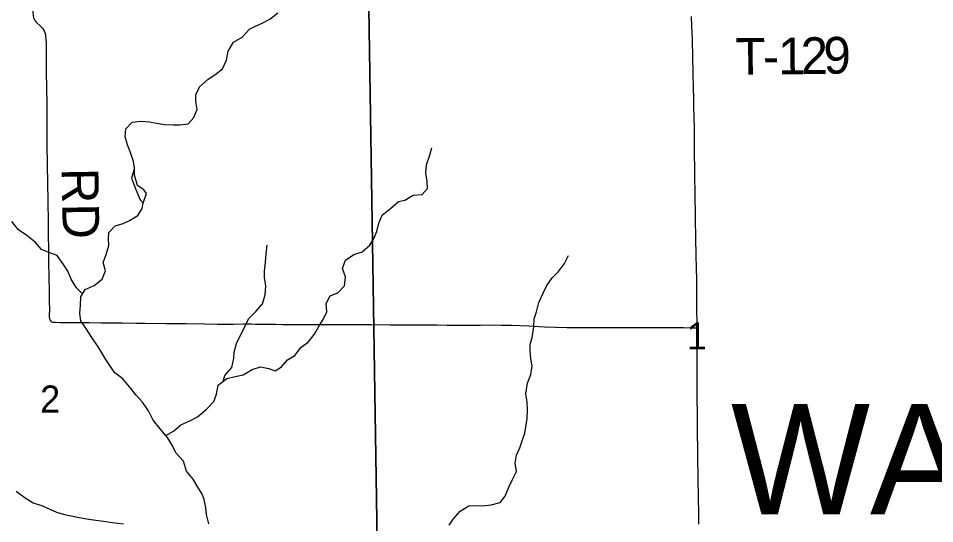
# Model space of a CAD drawing. Extents: x 0 to 1391, y -24 to 440.
# Drawn here: x 356.41 to 384.77, y 312.71 to 328.34 of the extents above; entities that cross this region are included whole.
import ezdxf

# ---------------------------------------------------------------- set-up
doc = ezdxf.new("R2010")
doc.units = 0
for name, color, linetype in [('GM_X_Minor_Lake', 7, 'Continuous'), ('GM_X_Minor_River', 7, 'Continuous'), ('GM_X_Section', 7, 'Continuous'), ('GM_X_Section_Text', 7, 'Continuous'), ('GM_X_Township_Road', 7, 'Continuous'), ('GM_X_Township_Road_Text', 7, 'Continuous'), ('GM_X_Township_Text', 7, 'Continuous')]:
    doc.layers.add(name, color=color, linetype=linetype)

msp = doc.modelspace()

# ---------------------------------------------------------------- linework, layer by layer
at = {"layer": 'GM_X_Minor_Lake'}
for points in [[(360.005, 323.718), (359.918, 323.397), (360.048, 323.045), (360.185, 322.724), (360.279, 322.625)], [(360.279, 322.625), (360.379, 322.917), (360.298, 323.033), (360.103, 323.173), (360.011, 323.486), (360.005, 323.718)]]:
    msp.add_lwpolyline(points, dxfattribs=at)
at = {"layer": 'GM_X_Minor_River'}
for points in [[(363.338, 327.755), (363.564, 328.007), (363.755, 328.102), (363.955, 328.188), (364.193, 328.319), (364.44, 328.51)], [(360.005, 323.718), (359.979, 323.91), (359.894, 324.162), (359.794, 324.423), (359.724, 324.675), (359.738, 324.917), (359.94, 325.133), (360.206, 325.164), (360.471, 325.135), (360.689, 325.092), (360.939, 325.056), (361.219, 325.042), (361.408, 325.045), (361.667, 325.077), (361.846, 325.277), (361.943, 325.518), (361.911, 325.769), (361.908, 325.974), (362.02, 326.222), (362.284, 326.459), (362.491, 326.591), (362.731, 326.782), (362.858, 327.045), (362.903, 327.325), (363.069, 327.602), (363.338, 327.755)], [(360.981, 315.436), (361.212, 315.57), (361.444, 315.762), (361.719, 315.884), (361.957, 316.015), (362.228, 316.244), (362.461, 316.482), (362.543, 316.715), (362.602, 316.987), (362.865, 317.201), (363.124, 317.263), (363.376, 317.31), (363.652, 317.478), (363.904, 317.556), (364.169, 317.511), (364.364, 317.438), (364.556, 317.555), (364.743, 317.771), (364.974, 317.91), (365.17, 318.163), (365.378, 318.318), (365.581, 318.571), (365.724, 318.826), (365.842, 319.02), (365.961, 319.26), (365.937, 319.519), (366.064, 319.751), (366.302, 319.852), (366.504, 320.067), (366.533, 320.34), (366.448, 320.6), (366.538, 320.856), (366.792, 321.039), (367.052, 321.117), (367.292, 321.324), (367.418, 321.526), (367.507, 321.744), (367.574, 322.008), (367.67, 322.256), (367.933, 322.462), (368.181, 322.676), (368.371, 322.717), (368.633, 322.871), (368.913, 322.887), (369.077, 323.08), (369.06, 323.293), (369.028, 323.552), (369.049, 323.81), (369.139, 324.073), (369.206, 324.337)], [(362.31, 312.698), (362.241, 312.995), (362.216, 313.209), (362.169, 313.452), (362.09, 313.644), (361.937, 313.891), (361.82, 314.083), (361.614, 314.331), (361.523, 314.637), (361.286, 314.9), (361.178, 315.138), (361.033, 315.377), (360.804, 315.64), (360.583, 315.911), (360.438, 316.195), (360.255, 316.465), (360.063, 316.682), (359.857, 316.938), (359.644, 317.193), (359.405, 317.373), (359.266, 317.566), (359.105, 317.821), (358.989, 318.013), (358.865, 318.213), (358.689, 318.468), (358.528, 318.722), (358.352, 318.977), (358.32, 319.213), (358.341, 319.463), (358.348, 319.728), (358.482, 319.953), (358.758, 320.075), (359.005, 320.267), (359.11, 320.53), (359.04, 320.79), (359.137, 321.038), (359.219, 321.317), (359.209, 321.514), (359.214, 321.712), (359.408, 321.919), (359.653, 321.997), (359.852, 322.091), (360.113, 322.237), (360.247, 322.454), (360.279, 322.625)], [(358.398, 319.813), (358.218, 320.004), (358.05, 320.266), (357.942, 320.519), (357.789, 320.758), (357.613, 321.005), (357.387, 321.087), (357.132, 321.184), (356.94, 321.416), (356.672, 321.619), (356.419, 321.8), (356.213, 322.055)], [(362.75, 317.107), (362.799, 317.293), (363.017, 317.539), (363.085, 317.825), (363.097, 318.015), (363.164, 318.279), (363.291, 318.534), (363.419, 318.797), (363.538, 319.044), (363.764, 319.274), (363.966, 319.512), (364.057, 319.791), (364.071, 320.056), (364.032, 320.33), (364.029, 320.52), (364.058, 320.8), (364.079, 321.058), (364.116, 321.323)], [(369.742, 312.656), (369.867, 312.851), (370.091, 313.09), (370.351, 313.261), (370.548, 313.265), (370.791, 313.261), (371.05, 313.295), (371.324, 313.359), (371.479, 313.561), (371.597, 313.832), (371.699, 314.058), (371.832, 314.322), (371.791, 314.581), (371.833, 314.823), (371.928, 315.049), (372.015, 315.298), (372.087, 315.51), (372.129, 315.767), (372.155, 315.964), (372.174, 316.237), (372.163, 316.465), (372.114, 316.724), (372.173, 317.057), (372.268, 317.321), (372.31, 317.586), (372.276, 317.807), (372.25, 318.066), (372.253, 318.255), (372.309, 318.467), (372.368, 318.793), (372.379, 319.043), (372.444, 319.262), (372.524, 319.549), (372.642, 319.821), (372.768, 320.077), (372.931, 320.317), (373.131, 320.511), (373.317, 320.759), (373.443, 321.007)], [(356.346, 313.711), (356.622, 313.507), (356.868, 313.357), (357.132, 313.268), (357.364, 313.171), (357.597, 313.067), (357.845, 312.993), (358.049, 312.95), (358.298, 312.899), (358.592, 312.846), (358.811, 312.818), (359.045, 312.782), (359.317, 312.746), (359.665, 312.699)]]:
    msp.add_lwpolyline(points, dxfattribs=at)
at = {"layer": 'GM_X_Section'}
for points in [[(366.91, 328.665), (367.258, 328.65), (367.565, 308.841), (347.482, 309.199), (347.266, 329.014)], [(387.293, 328.839), (387.556, 309.121), (387.563, 308.758), (367.565, 308.841), (367.258, 328.65)]]:
    msp.add_lwpolyline(points, close=True, dxfattribs=at)
at = {"layer": 'GM_X_Township_Road'}
for points in [[(356.872, 328.956), (356.861, 328.521), (356.868, 328.436), (356.887, 328.353), (356.923, 328.277), (356.976, 328.211), (357.094, 328.103), (357.148, 328.05), (357.187, 328), (357.214, 327.957), (357.239, 327.898), (357.253, 327.836), (357.258, 327.789)], [(377.42, 318.762), (377.42, 318.785), (377.414, 319.444), (377.413, 319.555), (377.409, 319.829), (377.405, 320.152), (377.397, 320.711), (377.393, 320.897), (377.39, 321.046), (377.38, 321.506), (377.369, 322.165), (377.365, 322.376), (377.364, 322.5), (377.362, 322.612), (377.359, 322.773), (377.356, 322.947), (377.355, 323.009), (377.35, 323.369), (377.339, 324.475), (377.333, 324.997), (377.329, 325.233), (377.32, 325.668), (377.315, 325.904), (377.309, 326.14), (377.305, 326.314), (377.3, 326.5), (377.293, 326.811), (377.289, 326.972), (377.286, 327.084), (377.271, 327.717), (377.258, 328.102), (377.245, 328.4)], [(357.258, 327.789), (357.265, 327.711), (357.272, 327.574), (357.278, 327.064), (357.278, 326.754), (357.288, 326.108), (357.295, 325.772), (357.299, 325.325), (357.299, 325.064), (357.299, 324.703), (357.301, 324.517), (357.306, 323.722), (357.312, 323.325), (357.316, 323.101), (357.323, 322.841), (357.328, 322.568), (357.334, 322.159), (357.336, 321.985), (357.339, 321.712), (357.347, 321.116), (357.352, 320.768), (357.358, 320.37), (357.365, 319.861), (357.365, 319.81), (357.367, 319.787), (357.373, 319.526), (357.374, 319.389), (357.374, 319.289), (357.372, 319.203), (357.373, 319.105), (357.379, 319.057), (357.391, 319.012), (357.416, 318.974), (357.444, 318.955), (357.477, 318.945), (357.562, 318.936), (357.722, 318.933), (357.958, 318.931), (358.244, 318.931), (358.604, 318.928), (358.977, 318.925), (359.324, 318.922), (359.622, 318.92), (360.057, 318.915), (360.33, 318.91), (360.974, 318.901), (361.247, 318.899), (361.409, 318.898), (361.608, 318.896), (362.179, 318.888), (362.564, 318.882), (362.762, 318.883), (363.073, 318.883), (363.37, 318.887), (363.507, 318.887), (363.619, 318.887), (363.755, 318.884), (363.978, 318.878), (364.027, 318.877), (364.113, 318.877), (364.225, 318.877), (364.262, 318.876), (364.386, 318.875), (364.597, 318.872), (364.82, 318.871), (365.292, 318.87), (365.478, 318.871), (365.739, 318.867), (365.85, 318.867), (366.136, 318.866), (366.384, 318.865), (366.805, 318.866), (367.091, 318.867), (367.314, 318.866), (367.923, 318.862), (368.37, 318.863), (368.818, 318.861), (369.377, 318.854), (369.688, 318.852), (370.284, 318.852), (370.47, 318.853), (370.719, 318.853), (371.017, 318.854), (371.365, 318.853), (371.688, 318.848), (372.21, 318.826), (372.694, 318.799), (373.041, 318.785), (373.401, 318.778), (373.786, 318.777), (374.296, 318.776), (374.718, 318.776), (374.867, 318.777), (375.079, 318.777), (375.538, 318.777), (375.973, 318.775), (376.408, 318.777), (376.582, 318.776), (376.992, 318.774), (377.279, 318.767), (377.316, 318.766), (377.42, 318.762)], [(377.472, 312.697), (377.471, 312.847), (377.47, 312.971), (377.46, 313.567), (377.457, 313.741), (377.454, 313.903), (377.447, 314.387), (377.445, 314.511), (377.439, 315.008), (377.438, 315.145), (377.437, 315.195), (377.435, 315.331), (377.434, 315.517), (377.426, 316.201), (377.422, 316.474), (377.421, 316.549), (377.421, 316.822), (377.42, 317.282), (377.419, 317.394), (377.418, 317.505), (377.418, 317.543), (377.415, 317.791), (377.418, 318.263), (377.419, 318.387), (377.42, 318.762)]]:
    msp.add_lwpolyline(points, dxfattribs=at)

# ---------------------------------------------------------------- texts
at = {"layer": 'GM_X_Section_Text'}
for s, p in [('1', (377.099, 318.097)), ('2', (357.09, 316.145))]:
    msp.add_text(s, height=0.837, rotation=0, dxfattribs=at).set_placement(p)
at = {"layer": 'GM_X_Township_Road_Text'}
for s, height, rotation, p in [('T', 1.136, 0.5914, (378.611, 326.59)), ('1', 1.136, 0.6301, (379.928, 326.604)), ('2', 1.136, 0.7763, (380.631, 326.612)), ('9', 1.136, 1.2822, (381.342, 326.621)), ('-', 1.136, 0.5914, (379.461, 326.599)), ('RD', 1.1364, 270.9724, (357.754, 323.702))]:
    msp.add_text(s, height=height, rotation=rotation, dxfattribs=at).set_placement(p)
at = {"layer": 'GM_X_Township_Text'}
msp.add_text('WASHINGTON', height=3.4091, rotation=0, dxfattribs=at).set_placement((378.466, 312.997))

doc.saveas('drawing.dxf')
